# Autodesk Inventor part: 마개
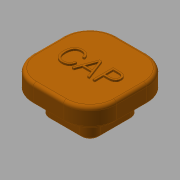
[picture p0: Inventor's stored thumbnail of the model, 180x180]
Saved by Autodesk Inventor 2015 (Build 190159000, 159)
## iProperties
Created: 2018-03
Part Number: 마개
Material: 고무
Document SubType Name: Modeling
Designer: mduedu
Density: 1 g/cm^3
Appearance: 주황색
Author: mduedu
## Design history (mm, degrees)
sketch "스케치1"
  geometry: L1 (12.5, 12.5)-(-12.5, 12.5); L2 (-12.5, 12.5)-(-12.5, -12.5); L3 (-12.5, -12.5)-(12.5, -12.5); L4 (12.5, -12.5)-(12.5, 12.5); L5 (12.5, 12.5)-(-12.5, -12.5); L6 (-12.5, 12.5)-(12.5, -12.5); 1 further point
  constraints: 12 end point, 2 midpoint, 2 parallel, 1 horizontal, 1 perpendicular
  dimensions: "d0" = 25 distance of L3.end L2.end; "d1" = 25 distance of L2.end L1.end
extrude "돌출1" new body sketch "스케치1" distance "d2" = 6; taper "d3" = 0 deg
fillet "모깎기1" dims "d4" = 8
fillet "모깎기2" dims "d5" = 1
sketch "스케치2"
  geometry: L1 (4.5, -12.5)-(-4.5, -12.5) reference; L2 (12.5, 4.5)-(12.5, -4.5) reference; L3 (-4.5, 12.5)-(4.5, 12.5) reference; L4 (-12.5, -4.5)-(-12.5, 4.5) reference; L5 (7.5, 4.5)-(7.5, -4.5); L6 (4.5, -7.5)-(-4.5, -7.5); L7 (-7.5, -4.5)-(-7.5, 4.5); L8 (-4.5, 7.5)-(4.5, 7.5); A1 r 8 centre (-4.5, -4.5) between (-12.5, -4.5) and (-4.5, -12.5) reference; A2 r 8 centre (4.5, -4.5) between (4.5, -12.5) and (12.5, -4.5) reference; A3 r 8 centre (4.5, 4.5) between (12.5, 4.5) and (4.5, 12.5) reference; A4 r 8 centre (-4.5, 4.5) between (-4.5, 12.5) and (-12.5, 4.5) reference; A5 r 3 centre (4.5, 4.5) between (7.5, 4.5) and (4.5, 7.5); A6 r 3 centre (4.5, -4.5) between (4.5, -7.5) and (7.5, -4.5); A7 r 3 centre (-4.5, -4.5) between (-7.5, -4.5) and (-4.5, -7.5); A8 r 3 centre (-4.5, 4.5) between (-4.5, 7.5) and (-7.5, 4.5); 1 further point
  constraints: 8 end point, 8 point on circle, 4 centre point, 7 other
  dimensions: "d6" = 5 distance between parallel lines of L8 L3
extrude "돌출2" join sketch "스케치2" distance "d7" = 6; taper "d8" = 0 deg
sketch "스케치3"
  geometry: L1 (4.5, 7.5)-(-4.5, 7.5) reference; L2 (-7.5, 4.5)-(-7.5, -4.5) reference; L3 (-4.5, -7.5)-(4.5, -7.5) reference; L4 (7.5, -4.5)-(7.5, 4.5) reference; L5 (-4.5, 5)-(4.5, 5); L6 (5, 4.5)-(5, -4.5); L7 (4.5, -5)-(-4.5, -5); L8 (-5, -4.5)-(-5, 4.5); A1 r 3 centre (4.5, 4.5) between (7.5, 4.5) and (4.5, 7.5) reference; A2 r 3 centre (-4.5, 4.5) between (-4.5, 7.5) and (-7.5, 4.5) reference; A3 r 3 centre (-4.5, -4.5) between (-7.5, -4.5) and (-4.5, -7.5) reference; A4 r 3 centre (4.5, -4.5) between (4.5, -7.5) and (7.5, -4.5) reference; A5 r 0.5 centre (4.5, 4.5) between (5, 4.5) and (4.5, 5); A6 r 0.5 centre (4.5, -4.5) between (4.5, -5) and (5, -4.5); A7 r 0.5 centre (-4.5, -4.5) between (-5, -4.5) and (-4.5, -5); A8 r 0.5 centre (-4.5, 4.5) between (-4.5, 5) and (-5, 4.5); 1 further point
  constraints: 8 end point, 8 point on circle, 4 centre point, 7 other
  dimensions: "d9" = 2.5 distance between parallel lines of L5 L1
extrude "돌출3" cut sketch "스케치3" stored distance "d10" = 10; taper "d11" = 0 deg
fillet "모깎기3" dims "d12" = 1
sketch "스케치4"
  geometry: L1 (7.5, 4.5)-(7.5, -4.5) reference; L2 (4.5, -7.5)-(-4.5, -7.5) reference; L3 (-7.5, -4.5)-(-7.5, 4.5) reference; L4 (-4.5, 7.5)-(4.5, 7.5) reference; L5 (4.5, -12.5)-(-4.5, -12.5) reference; L6 (12.5, 4.5)-(12.5, -4.5) reference; L7 (-4.5, 12.5)-(4.5, 12.5) reference; L8 (-12.5, -4.5)-(-12.5, 4.5) reference; L9 (11.5, 4.5)-(11.5, -4.5); L10 (4.5, -11.5)-(-4.5, -11.5); L11 (-11.5, -4.5)-(-11.5, 4.5); L12 (-4.5, 11.5)-(4.5, 11.5); A1 r 3 centre (4.5, -4.5) between (4.5, -7.5) and (7.5, -4.5) reference; A2 r 3 centre (-4.5, -4.5) between (-7.5, -4.5) and (-4.5, -7.5) reference; A3 r 3 centre (-4.5, 4.5) between (-4.5, 7.5) and (-7.5, 4.5) reference; A4 r 3 centre (4.5, 4.5) between (7.5, 4.5) and (4.5, 7.5) reference; A5 r 8 centre (-4.5, -4.5) between (-12.5, -4.5) and (-4.5, -12.5) reference; A6 r 8 centre (4.5, -4.5) between (4.5, -12.5) and (12.5, -4.5) reference; A7 r 8 centre (4.5, 4.5) between (12.5, 4.5) and (4.5, 12.5) reference; A8 r 8 centre (-4.5, 4.5) between (-4.5, 12.5) and (-12.5, 4.5) reference; A9 r 7 centre (4.5, 4.5) between (11.5, 4.5) and (4.5, 11.5); A10 r 7 centre (4.5, -4.5) between (4.5, -11.5) and (11.5, -4.5); A11 r 7 centre (-4.5, -4.5) between (-11.5, -4.5) and (-4.5, -11.5); A12 r 7 centre (-4.5, 4.5) between (-4.5, 11.5) and (-11.5, 4.5); 1 further point
  constraints: 8 end point, 8 point on circle, 4 centre point, 7 other
  dimensions: "d13" = 1 distance between parallel lines of L12 L7
extrude "돌출4" cut sketch "스케치4" distance "d14" = 1; taper "d15" = 0 deg
chamfer "모따기1" distance "d16" = 0.5; stored, may be unused: second distance "d17" = 2, angle "d18" = 45 deg
sketch "스케치5"
  geometry: 2 further points
  constraints: 1 coincident, 1 other
feature "엠보싱1" sketch "스케치5" dims "d0" = 25, "d1" = 25, "d19" = 0.5, "d20" = 0
node "솔리드1"
node "투영된 루프1"
node "투영된 루프2"
node "투영된 루프3"
